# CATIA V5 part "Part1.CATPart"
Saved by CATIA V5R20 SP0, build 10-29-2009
Part number: Part1
Bounding box of the stored display mesh (mm): x -23 to 41, y -104 to 104, z 0 to 72
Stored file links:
  C:\Users\hojat azimi\Desktop\New folder\Part1.CATPart
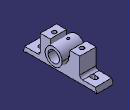
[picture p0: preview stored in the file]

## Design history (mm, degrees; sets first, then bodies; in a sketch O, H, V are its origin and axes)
Body1 (main body)
  Sketch1 on yz-plane, origin (0, 0, 0), H (0, 1, 0), V (0, 0, 1)
    point P1 (0, 2)
    line L1 (0, 2) -> (-97.5, 2)
    line L2 (-97.5, 2) -> (-97.5, 0)
    line L3 (-97.5, 0) -> (-104, 0)
    point P4 (-104, 0)
    point P5 (-104, 0)
    line L4 (-104, 0) -> (-99.9856, 14)
    point P6 (-99.9856, 14)
    point P7 (0, 0)
    point P8 (0, 2)
    point P11 (104, 0)
    point P12 (104, 0)
    line L5 (0, 2) -> (97.5, 2)
    line L6 (97.5, 2) -> (97.5, 0)
    line L7 (97.5, 0) -> (104, 0)
    line L8 (104, 0) -> (99.9856, 14)
    point P15 (-24, 48)
    point P16 (-28, 68)
    line L9 (-28, 68) -> (-28, 52)
    line L10 (-28, 52) -> (-23.6643, 52)
    point P19 (24, 48)
    line L11 (28, 68) -> (28, 52)
    line L12 (28, 52) -> (23.6643, 52)
    arc A1 centre (0, 48) radius 24 from (-23.6643, 52) to (23.6643, 52) ccw
    line L13 (64, 14) -> (99.9856, 14)
    line L14 (56, 22) -> (56, 68)
    line L15 (56, 68) -> (28, 68)
    point P24 (-28, 68)
    line L16 (-56, 68) -> (-28, 68)
    line L17 (-56, 22) -> (-56, 68)
    point P26 (-99.9856, 14)
    line L18 (-64, 14) -> (-99.9856, 14)
    arc A2 centre (64, 22) radius 8 from (64, 14) to (56, 22) cw
    arc A3 centre (-64, 22) radius 8 from (-56, 22) to (-64, 14) cw
    coincidence: P1 P8, P4 P5, P6 P26, P11 P12, P16 P24
  Pad1: profile Sketch1, direction (1, 0, 0), length 23, mirrored extent
  Sketch2 on face of Pad1 from Sketch1.L15, origin (0, 0, 68), H (1, 0, 0), V (0, 1, 0)
    construction line L1 (0, 77) -> (0, 69)
    line L2 (6, 77) -> (6, 69)
    line L3 (-6, 69) -> (-6, 77)
    arc A1 centre (0, 69) radius 6 from (6, 69) to (-6, 69) cw
    arc A2 centre (0, 77) radius 6 from (-6, 77) to (6, 77) cw
    arc A3 centre (0, -77) radius 6 from (-6, -77) to (6, -77) ccw
    line L4 (6, -77) -> (6, -69)
    line L5 (-6, -69) -> (-6, -77)
    arc A4 centre (0, -69) radius 6 from (6, -69) to (-6, -69) ccw
  Sketch3 on face of Pad1 from Sketch1.L15, origin (0, 0, 68), H (1, 0, 0), V (0, 1, 0)
    circle A1 centre (0, 39) radius 6
    circle A2 centre (0, -39) radius 6
  Pocket1: profile Sketch3, direction (0, 0, -1), through (limit type 3)
  Pocket2: profile Sketch2, direction (0, 0, -1), through (limit type 3)
  Sketch4 on face of Pad1 from Sketch1.L15, origin (0, 0, 68), H (1, 0, 0), V (0, 1, 0)
    circle A1 centre (0, 0) radius 4
  Pocket3: profile Sketch4, direction (0, 0, -1), length 52
  Sketch5 on end face of Pad1, origin (23, 0, 0), H (0, 1, 0), V (0, 0, 1)
    circle A1 centre (0, 48) radius 24
    circle A2 centre (0, 48) radius 16
  Pad2: profile Sketch5, direction (1, 0, 0), length 18, opposite side length 46
  Sketch6 on face of Pad1 from Sketch1.L15, origin (0, 0, 68), H (1, 0, 0), V (0, 1, 0)
    circle A1 centre (0, 0) radius 4
  Pocket4: profile Sketch6, direction (0, 0, -1), length 59, opposite side length 11
  Sketch7 on face of Pad1 from Sketch1.L5, origin (0, 0, 2), H (1, 0, 0), V (0, -1, 0)
    line L1 (-14, -30.9171) -> (-14, -47.0829)
    line L2 (-14, -47.0829) -> (0, -55.1658)
    line L3 (0, -55.1658) -> (14, -47.0829)
    line L4 (14, -47.0829) -> (14, -30.9171)
    line L5 (14, -30.9171) -> (0, -22.8342)
    line L6 (0, -22.8342) -> (-14, -30.9171)
    line L7 (-14, 30.9171) -> (-14, 47.0829)
    line L8 (-14, 47.0829) -> (0, 55.1658)
    line L9 (0, 55.1658) -> (14, 47.0829)
    line L10 (14, 47.0829) -> (14, 30.9171)
    line L11 (14, 30.9171) -> (0, 22.8342)
    line L12 (0, 22.8342) -> (-14, 30.9171)
  Pocket5: profile Sketch7, direction (0, 0, 1), length 10
  Sketch8 on face of Pad1 from Sketch1.L5, origin (-2, 0, 2), H (0, 1, 0), V (1, 0, 0)
    point P1 (0, 2)
    line L1 (0, 2) -> (-97.5, 2)
    line L2 (-97.5, 2) -> (-97.5, 0)
    line L3 (-97.5, 0) -> (-104, 0)
    point P4 (-104, 0)
    point P5 (-104, 0)
    line L4 (-104, 0) -> (-99.9856, 14)
    point P6 (-99.9856, 14)
    point P7 (0, 0)
    point P8 (0, 2)
    point P11 (104, 0)
    point P12 (104, 0)
    line L5 (0, 2) -> (97.5, 2)
    line L6 (97.5, 2) -> (97.5, 0)
    line L7 (97.5, 0) -> (104, 0)
    line L8 (104, 0) -> (99.9856, 14)
    point P15 (-24, 48)
    point P16 (-28, 68)
    line L9 (-28, 68) -> (-28, 52)
    line L10 (-28, 52) -> (-23.6643, 52)
    point P19 (24, 48)
    line L11 (28, 68) -> (28, 52)
    line L12 (28, 52) -> (23.6643, 52)
    arc A1 centre (0, 48) radius 24 from (-23.6643, 52) to (23.6643, 52) ccw
    line L13 (64, 14) -> (99.9856, 14)
    line L14 (56, 22) -> (56, 68)
    line L15 (56, 68) -> (28, 68)
    point P24 (-28, 68)
    line L16 (-56, 68) -> (-28, 68)
    line L17 (-56, 22) -> (-56, 68)
    point P26 (-99.9856, 14)
    line L18 (-64, 14) -> (-99.9856, 14)
    arc A2 centre (64, 22) radius 8 from (64, 14) to (56, 22) cw
    arc A3 centre (-64, 22) radius 8 from (-56, 22) to (-64, 14) cw
    coincidence: P1 P8, P4 P5, P6 P26, P11 P12, P16 P24
  Pad3: profile Sketch8, direction (0, 0, -1), length 23, mirrored extent
  Sketch9 on face of Pad1 from Sketch1.L5, origin (-2, 0, 2), H (0, 1, 0), V (1, 0, 0)
    point P1 (0, 2)
    line L1 (0, 2) -> (-97.5, 2)
    line L2 (-97.5, 2) -> (-97.5, 0)
    line L3 (-97.5, 0) -> (-104, 0)
    point P4 (-104, 0)
    point P5 (-104, 0)
    line L4 (-104, 0) -> (-99.9856, 14)
    point P6 (-99.9856, 14)
    point P7 (0, 0)
    point P8 (0, 2)
    point P11 (104, 0)
    point P12 (104, 0)
    line L5 (0, 2) -> (97.5, 2)
    line L6 (97.5, 2) -> (97.5, 0)
    line L7 (97.5, 0) -> (104, 0)
    line L8 (104, 0) -> (99.9856, 14)
    point P15 (-24, 48)
    point P16 (-28, 68)
    line L9 (-28, 68) -> (-28, 52)
    line L10 (-28, 52) -> (-23.6643, 52)
    point P19 (24, 48)
    line L11 (28, 68) -> (28, 52)
    line L12 (28, 52) -> (23.6643, 52)
    arc A1 centre (0, 48) radius 24 from (-23.6643, 52) to (23.6643, 52) ccw
    line L13 (64, 14) -> (99.9856, 14)
    line L14 (56, 22) -> (56, 68)
    line L15 (56, 68) -> (28, 68)
    point P24 (-28, 68)
    line L16 (-56, 68) -> (-28, 68)
    line L17 (-56, 22) -> (-56, 68)
    point P26 (-99.9856, 14)
    line L18 (-64, 14) -> (-99.9856, 14)
    arc A2 centre (64, 22) radius 8 from (64, 14) to (56, 22) cw
    arc A3 centre (-64, 22) radius 8 from (-56, 22) to (-64, 14) cw
    coincidence: P1 P8, P4 P5, P6 P26, P11 P12, P16 P24
  Pad4: profile Sketch9, direction (0, 0, -1), length 23, mirrored extent
Current feature: Pocket5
